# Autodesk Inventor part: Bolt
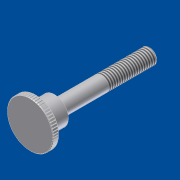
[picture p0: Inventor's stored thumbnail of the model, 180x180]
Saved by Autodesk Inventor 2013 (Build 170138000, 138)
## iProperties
Shininess: 69.0
Length Units: 11269
Angle Units: 11279
Time Units: 11290
Mass Units: 11283
Length Display Precision: 3
Angle Display Precision: 2
Created: 2001-04
Part Number: Bolt
Material: Standard
Document SubType Name: Modellieren
Designer: dl
Density: 1 g/cm^3
Density: 0.0
Volumn: 0.0
Area: 0.0
PropertySet Name: Model Information
Control State: 0
Master: False
Checked Out: False
Author: dl
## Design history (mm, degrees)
body "Solid1"
sketch "Sketch1"
  geometry: C1 r 2.5 at (3.846, 1.324)
  constraints: 1 centre point
  dimensions: "d0" = 5 diameter of C1 (= Durchmesser)
extrude "Extrusion1" new body sketch "Sketch1" distance "d1" = 39 (computed from Klemmlänge); taper "d2" = 0 deg
thread "Thread1" dims "d3" = 16, "d4" = 0
chamfer "Chamfer1" distance "d5" = 0.4; stored, may be unused: second distance "d6" = 0.4, angle "d31" = 45 deg
node "Sketch2"
workaxis "Work Axis1"
workplane "Work Plane1"
revolve "Revolution1" stored, may be unused: angle "d17" = 90 deg
sketch "Sketch4"
  geometry: L1 (-8.3, -0.5)-(-8.3, 0.5); L2 (-8.3, 0.5)-(-7.3, 0); L3 (-7.3, 0)-(-8.3, -0.5); C1 r 7.5 at (0, 0) reference
  constraints: 6 end point, 1 vertical
  dimensions: "d18" = 1 distance of L1.start L1.end; "d19" = 0.5 vertical distance of L2.end L1.start; "d20" = 1 horizontal distance of L2.end L1.start; "d21" = 7.3 distance of C1.centre L2.end; "d22" = 0 vertical distance of C1.centre L2.end
chamfer "Chamfer2" distance "d23" = 0.2; stored, may be unused: second distance "d24" = 2, angle "d32" = 45 deg
extrude "Extrusion2" cut sketch "Sketch4" stored distance "d25" = 10; taper "d26" = 0 deg
pattern_circular "Circular Pattern1" dims angle "d29" = 360 deg
sketch "Sketch3"
  geometry: L1 (39, 2.5)-(39, -2.5) reference; L2 (39, 0)-(39, 7.5); L3 (39, 7.5)-(37, 7.5); L4 (37, 7.5)-(37, 4.5); L5 (37, 4.5)-(31, 4.5); L6 (31, 4.5)-(31, 0); L7 (31, 0)-(39, 0); L8 (-3.9, 0)-(50.7, 0) reference
  constraints: 12 end point, 3 parallel, 2 perpendicular, 1 collinear, 1 midpoint
  dimensions: "d13" = 4.5 distance of L5.end L6.end; "d14" = 7.5 distance of L2.start L2.end; "d15" = 8 distance between parallel lines of L2 L6; "d16" = 2 distance of L2.end L3.end
other parameters: "d12" = 90 deg, "d30" = 0, "Durchmesser" = 5 [user parameter; used in 1 equation term], "Klemmlänge" = 15 [user parameter; used in 1 equation term]
